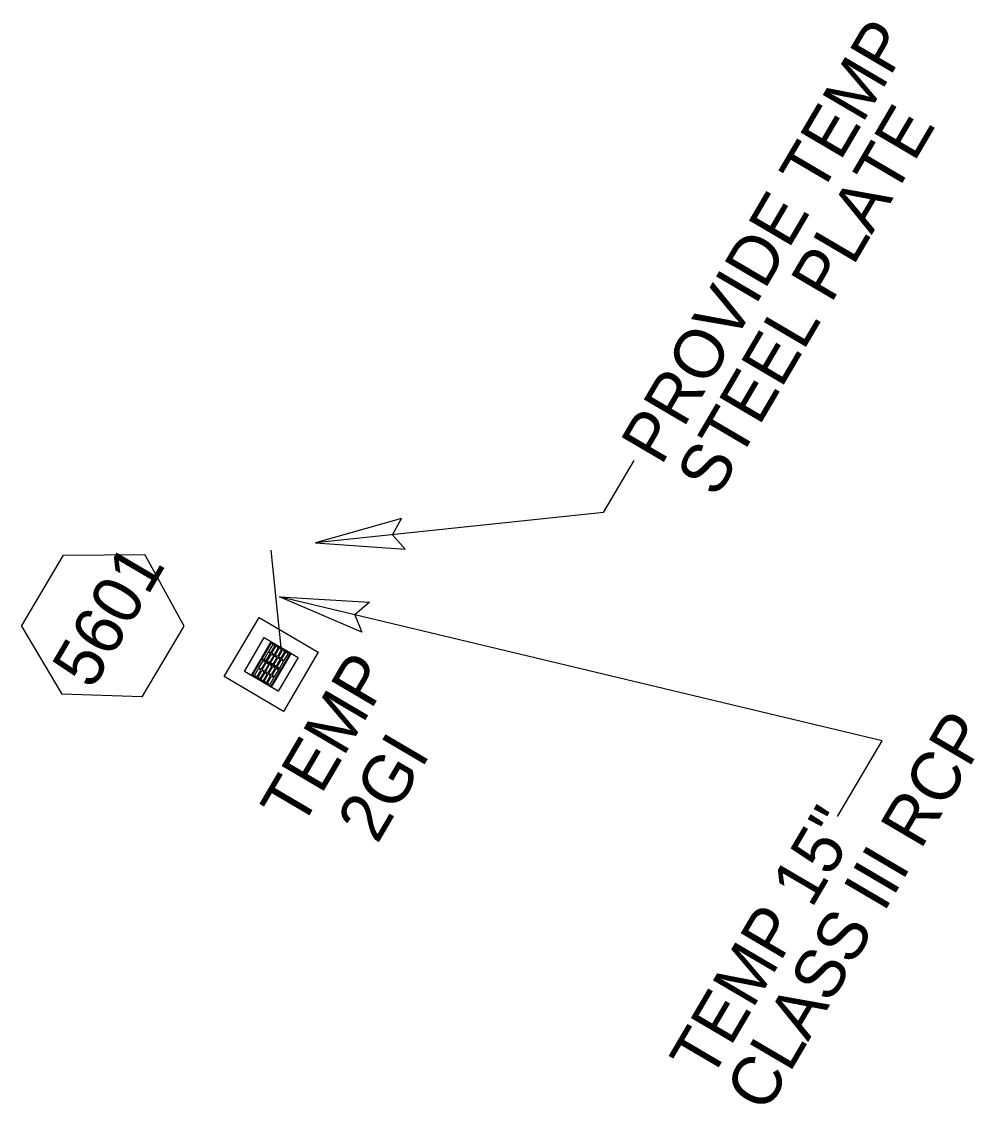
# Model space of a CAD drawing. Extents: x 2214978 to 2238755, y 984122 to 1016255.
# Drawn here: x 2238657.4 to 2238754.6, y 1016144.2 to 1016254.7 of the extents above; entities that cross this region are included whole.
import ezdxf

# ---------------------------------------------------------------- set-up
doc = ezdxf.new("R2010")
doc.units = 0
for name, color, linetype in [('Prop Drainage Structure Box Number Symbol CELL', 7, 'Continuous'), ('Prop Drainage Structure Drop Inlet Grate 2 Wide Slots and Sag Grates 840 22 CELL', 7, 'Continuous'), ('Prop Drainage Structure Drop Inlet Grate 2 Wide Slots and Sag Grates 840 22 Label', 7, 'Continuous'), ('Prop Drainage Structure Pipe RCP 15in Class III', 7, 'Continuous'), ('Prop Drainage Structure Plot Symbol 20 Scale', 7, 'Continuous'), ('Prop Drainage Structure Plot Symbol 50 Scale', 7, 'Continuous'), ('Prop Plan Preparation Drainage Notes Label', 7, 'Continuous')]:
    doc.layers.add(name, color=color, linetype=linetype)

msp = doc.modelspace()

# ---------------------------------------------------------------- linework, layer by layer
at = {"layer": 'Prop Drainage Structure Box Number Symbol CELL'}
for p, q in [((2238657.43, 1016192.99), (2238661.69, 1016200.23)), ((2238661.69, 1016200.23), (2238670, 1016200.29)), ((2238674, 1016192.99), (2238670, 1016200.29)), ((2238657.43, 1016192.99), (2238661.54, 1016186.03)), ((2238669.74, 1016185.76), (2238674, 1016192.99)), ((2238669.74, 1016185.76), (2238661.54, 1016186.03))]:
    msp.add_line(p, q, dxfattribs=at)
at = {"layer": 'Prop Drainage Structure Drop Inlet Grate 2 Wide Slots and Sag Grates 840 22 CELL'}
for p, q in [((2238683.9, 1016190.8), (2238683.9, 1016190.8)), ((2238681.88, 1016189.67), (2238681.88, 1016189.67)), ((2238682.89, 1016189.07), (2238682.89, 1016189.07)), ((2238683.9, 1016188.48), (2238683.9, 1016188.48)), ((2238681.88, 1016187.35), (2238681.88, 1016187.35))]:
    msp.add_line(p, q, dxfattribs=at)
for points in [[(2238680.87, 1016187.94), (2238682.9, 1016191.39), (2238684.91, 1016190.21), (2238682.88, 1016186.76), (2238680.87, 1016187.94)], [(2238680.96, 1016187.96), (2238682.92, 1016191.3), (2238684.82, 1016190.18), (2238682.86, 1016186.84), (2238680.96, 1016187.96)], [(2238681.95, 1016189.64), (2238682.92, 1016191.29), (2238684.81, 1016190.18), (2238683.84, 1016188.53), (2238681.95, 1016189.64)], [(2238682.85, 1016190.27), (2238683.28, 1016190.99), (2238683.04, 1016191.12), (2238682.62, 1016190.4), (2238682.85, 1016190.27)], [(2238682.39, 1016189.48), (2238682.81, 1016190.2), (2238682.58, 1016190.33), (2238682.16, 1016189.61), (2238682.39, 1016189.48)], [(2238682.49, 1016189.42), (2238682.91, 1016190.14), (2238683.14, 1016190), (2238682.72, 1016189.28), (2238682.49, 1016189.42)], [(2238682.82, 1016189.22), (2238683.24, 1016189.94), (2238683.48, 1016189.8), (2238683.05, 1016189.09), (2238682.82, 1016189.22)], [(2238682.95, 1016190.21), (2238683.37, 1016190.93), (2238683.61, 1016190.79), (2238683.19, 1016190.07), (2238682.95, 1016190.21)], [(2238683.28, 1016190.01), (2238683.71, 1016190.73), (2238683.94, 1016190.59), (2238683.52, 1016189.88), (2238683.28, 1016190.01)], [(2238683.62, 1016189.82), (2238684.04, 1016190.54), (2238684.27, 1016190.4), (2238683.85, 1016189.68), (2238683.62, 1016189.82)], [(2238683.95, 1016189.62), (2238684.37, 1016190.34), (2238684.61, 1016190.2), (2238684.18, 1016189.49), (2238683.95, 1016189.62)], [(2238680.97, 1016187.97), (2238681.94, 1016189.62), (2238683.83, 1016188.51), (2238682.86, 1016186.86), (2238680.97, 1016187.97)], [(2238681.64, 1016188.73), (2238682.06, 1016189.45), (2238682.29, 1016189.32), (2238681.87, 1016188.6), (2238681.64, 1016188.73)], [(2238681.97, 1016188.54), (2238682.39, 1016189.26), (2238682.63, 1016189.12), (2238682.2, 1016188.4), (2238681.97, 1016188.54)], [(2238682.3, 1016188.34), (2238682.73, 1016189.06), (2238682.96, 1016188.92), (2238682.54, 1016188.21), (2238682.3, 1016188.34)], [(2238682.64, 1016188.15), (2238683.06, 1016188.87), (2238683.29, 1016188.73), (2238682.87, 1016188.01), (2238682.64, 1016188.15)], [(2238683.15, 1016189.03), (2238683.57, 1016189.75), (2238683.81, 1016189.61), (2238683.39, 1016188.89), (2238683.15, 1016189.03)], [(2238683.48, 1016188.83), (2238683.91, 1016189.55), (2238684.14, 1016189.41), (2238683.72, 1016188.7), (2238683.48, 1016188.83)], [(2238681.17, 1016187.94), (2238681.6, 1016188.66), (2238681.83, 1016188.52), (2238681.41, 1016187.81), (2238681.17, 1016187.94)], [(2238681.51, 1016187.75), (2238681.93, 1016188.47), (2238682.16, 1016188.33), (2238681.74, 1016187.61), (2238681.51, 1016187.75)], [(2238681.84, 1016187.55), (2238682.26, 1016188.27), (2238682.49, 1016188.13), (2238682.07, 1016187.42), (2238681.84, 1016187.55)], [(2238682.17, 1016187.36), (2238682.59, 1016188.08), (2238682.83, 1016187.94), (2238682.4, 1016187.22), (2238682.17, 1016187.36)], [(2238682.5, 1016187.16), (2238682.93, 1016187.88), (2238683.16, 1016187.74), (2238682.74, 1016187.03), (2238682.5, 1016187.16)], [(2238682.97, 1016187.95), (2238683.39, 1016188.67), (2238683.62, 1016188.53), (2238683.2, 1016187.82), (2238682.97, 1016187.95)]]:
    msp.add_lwpolyline(points, dxfattribs=at)
at = {"layer": 'Prop Drainage Structure Pipe RCP 15in Class III'}
msp.add_line((2238683.9, 1016190.8), (2238682.89, 1016200.74), dxfattribs=at)
at = {"layer": 'Prop Drainage Structure Plot Symbol 20 Scale'}
msp.add_lwpolyline([(2238680.15, 1016188.36), (2238682.18, 1016191.81), (2238685.63, 1016189.78), (2238683.6, 1016186.34)], close=True, dxfattribs=at)
at = {"layer": 'Prop Drainage Structure Plot Symbol 50 Scale'}
msp.add_lwpolyline([(2238678.1, 1016187.83), (2238681.65, 1016193.86), (2238687.68, 1016190.32), (2238684.13, 1016184.28)], close=True, dxfattribs=at)
at = {"layer": 'Prop Plan Preparation Drainage Notes Label'}
for p, q in [((2238716.79, 1016204.57), (2238719.92, 1016209.89)), ((2238716.79, 1016204.57), (2238687.39, 1016201.49)), ((2238745.21, 1016181.28), (2238683.73, 1016195.98)), ((2238740.67, 1016173.56), (2238745.21, 1016181.28))]:
    msp.add_line(p, q, dxfattribs=at)
for points in [[(2238696.18, 1016203.97), (2238687.39, 1016201.49), (2238696.56, 1016200.84), (2238695.25, 1016202.31)], [(2238692.13, 1016192.38), (2238683.73, 1016195.98), (2238692.91, 1016195.44), (2238691.42, 1016194.15)]]:
    msp.add_lwpolyline(points, close=True, dxfattribs=at)

# ---------------------------------------------------------------- texts
at = {"layer": 'Prop Drainage Structure Box Number Symbol CELL'}
msp.add_text('5601', height=5, rotation=59.5521, dxfattribs=at).set_placement((2238664.62, 1016186.38))
at = {"layer": 'Prop Drainage Structure Drop Inlet Grate 2 Wide Slots and Sag Grates 840 22 Label'}
for s, p in [('TEMP', (2238685.91, 1016172.19)), ('2GI', (2238693.71, 1016170.66))]:
    msp.add_text(s, height=5, rotation=59.5521, dxfattribs=at).set_placement(p)
at = {"layer": 'Prop Plan Preparation Drainage Notes Label'}
for s, p in [('PROVIDE TEMP', (2238722.67, 1016209.26)), ('STEEL PLATE', (2238728.32, 1016205.94)), ('CLASS III RCP', (2238733.32, 1016143.16)), ('TEMP 15"', (2238727.66, 1016146.48))]:
    msp.add_text(s, height=5, rotation=59.566, dxfattribs=at).set_placement(p)

doc.saveas('drawing.dxf')
